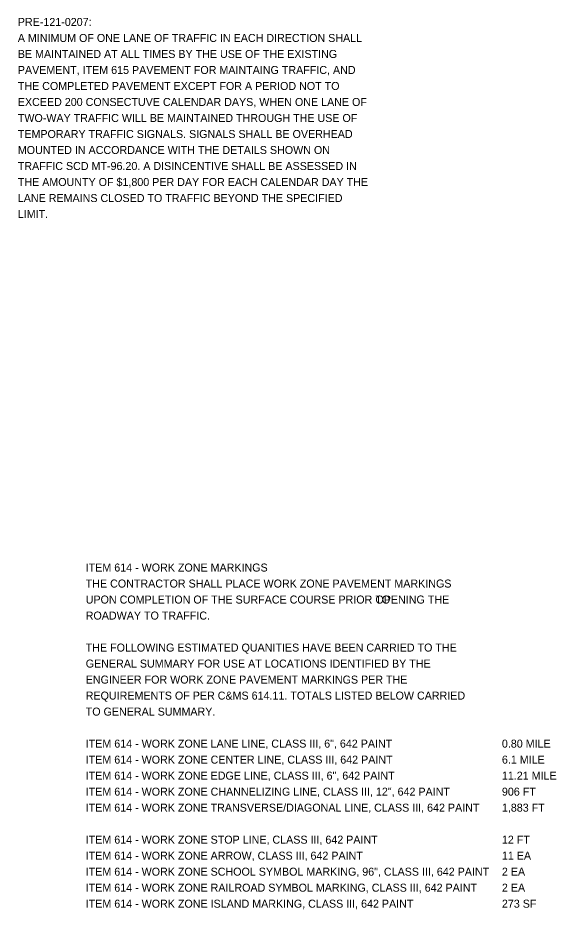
# Model space of a CAD drawing. Extents: x -59 to 65, y -13 to 46.
# Drawn here: x -13.77 to -4.35, y 2.47 to 18.06 of the extents above; entities that cross this region are included whole.
import ezdxf

# ---------------------------------------------------------------- set-up
doc = ezdxf.new("R2010")
doc.units = 0
doc.layers.add('SH_Text', color=7, linetype='Continuous')

msp = doc.modelspace()

# ---------------------------------------------------------------- texts
at = {"layer": 'SH_Text'}
for s, p in [('PRE-121-0207:', (-13.772, 17.92)), ('A MINIMUM OF ONE LANE OF TRAFFIC IN EACH DIRECTION SHALL ', (-13.772, 17.64)), ('BE MAINTAINED AT ALL TIMES BY THE USE OF THE EXISTING ', (-13.772, 17.36)), ('PAVEMENT, ITEM 615 PAVEMENT FOR MAINTAING TRAFFIC, AND ', (-13.772, 17.08)), ('THE COMPLETED PAVEMENT EXCEPT FOR A PERIOD NOT TO ', (-13.772, 16.8)), ('EXCEED 200 CONSECTUVE CALENDAR DAYS, WHEN ONE LANE OF ', (-13.772, 16.52)), ('TWO-WAY TRAFFIC WILL BE MAINTAINED THROUGH THE USE OF ', (-13.772, 16.24)), ('TEMPORARY TRAFFIC SIGNALS. SIGNALS SHALL BE OVERHEAD ', (-13.772, 15.96)), ('MOUNTED IN ACCORDANCE WITH THE DETAILS SHOWN ON ', (-13.772, 15.68)), ('TRAFFIC SCD MT-96.20. A DISINCENTIVE SHALL BE ASSESSED IN ', (-13.772, 15.4)), ('THE AMOUNTY OF $1,800 PER DAY FOR EACH CALENDAR DAY THE ', (-13.772, 15.12)), ('LANE REMAINS CLOSED TO TRAFFIC BEYOND THE SPECIFIED ', (-13.772, 14.84)), ('LIMIT.', (-13.772, 14.56)), ('ITEM 614 - WORK ZONE MARKINGS', (-12.584, 8.376)), ('THE CONTRACTOR SHALL PLACE WORK ZONE PAVEMENT MARKINGS ', (-12.584, 8.096)), ('UPON COMPLETION OF THE SURFACE COURSE PRIOR TO', (-12.584, 7.816)), ('OPENING THE ', (-7.516, 7.816)), ('ROADWAY TO TRAFFIC.', (-12.584, 7.536)), ('THE FOLLOWING ESTIMATED QUANITIES HAVE BEEN CARRIED TO THE ', (-12.584, 6.976)), ('GENERAL SUMMARY FOR USE AT LOCATIONS IDENTIFIED BY THE ', (-12.584, 6.696)), ('ENGINEER FOR WORK ZONE PAVEMENT MARKINGS PER THE ', (-12.584, 6.416)), ('REQUIREMENTS OF PER C&MS 614.11. TOTALS LISTED BELOW CARRIED ', (-12.584, 6.136)), ('TO GENERAL SUMMARY.', (-12.584, 5.856)), ('ITEM 614 - WORK ZONE LANE LINE, CLASS III, 6", 642 PAINT', (-12.584, 5.296)), ('0.80 MILE', (-5.304, 5.296)), ('ITEM 614 - WORK ZONE CENTER LINE, CLASS III, 642 PAINT', (-12.584, 5.016)), ('6.1 MILE', (-5.304, 5.016)), ('ITEM 614 - WORK ZONE EDGE LINE, CLASS III, 6", 642 PAINT', (-12.584, 4.736)), ('11.21 MILE', (-5.304, 4.736)), ('ITEM 614 - WORK ZONE CHANNELIZING LINE, CLASS III, 12", 642 PAINT    ', (-12.584, 4.456)), ('906 FT', (-5.304, 4.456)), ('ITEM 614 - WORK ZONE TRANSVERSE/DIAGONAL LINE, CLASS III, 642 PAINT ', (-12.584, 4.176)), ('1,883 FT', (-5.304, 4.176)), ('ITEM 614 - WORK ZONE STOP LINE, CLASS III, 642 PAINT', (-12.584, 3.616)), ('12 FT', (-5.304, 3.616)), ('ITEM 614 - WORK ZONE ARROW, CLASS III, 642 PAINT', (-12.584, 3.336)), ('11 EA', (-5.304, 3.336)), ('ITEM 614 - WORK ZONE SCHOOL SYMBOL MARKING, 96", CLASS III, 642 PAINT      ', (-12.584, 3.056)), ('2 EA', (-5.304, 3.056)), ('ITEM 614 - WORK ZONE RAILROAD SYMBOL MARKING, CLASS III, 642 PAINT', (-12.584, 2.776)), ('2 EA', (-5.304, 2.776)), ('ITEM 614 - WORK ZONE ISLAND MARKING, CLASS III, 642 PAINT', (-12.584, 2.496)), ('273 SF', (-5.304, 2.496))]:
    msp.add_text(s, height=0.14, dxfattribs=at).set_placement(p)

doc.saveas('drawing.dxf')
